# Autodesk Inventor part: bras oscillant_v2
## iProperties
Created: 2006-03
Part Number: bras oscillant_v2
Document SubType Name: Modeling
Designer: Flavien MARTY
Author: Flavien MARTY
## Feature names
1. Base1
